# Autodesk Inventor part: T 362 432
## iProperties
Created: 2006-04
Material: 6PA45/1GF30
Document SubType Name: Modeling
Designer: I.Baliuc
Part Number: T 362 432
Description: Halterung für Hilfsschalter
Density: 1.14 g/cm^3
Title: Halterung für Hilfsschalter
Company: Mayer & Müller AG Schaltgeräte
Rohabmessung: Granulat 384043
Zweck: Speicherantrieb
Author: T.Messerschmitt
Revision Number: 362432
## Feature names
1. Extrusion2
2. Extrusion3
3. R1_a [Fillet]
4. R1_b [Fillet]
5. Bohrung_Ø2.5 [Hole]
6. Bohrung2 [Hole]
